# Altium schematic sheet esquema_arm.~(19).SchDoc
size A4
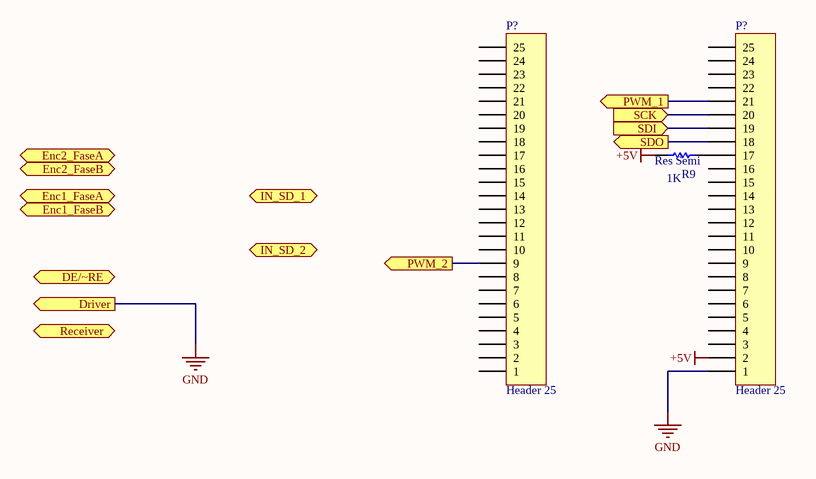
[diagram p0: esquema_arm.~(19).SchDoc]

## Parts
(Parts that share a designator on the sheet are numbered #1, #2 ... from top to bottom, then left to right.)
P?#1  Header 25  [HDR1X25]
P?#2  Header 25  [HDR1X25]
R9  Res Semi  value 1K  [1005[0402]]

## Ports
DE/~RE (out), Driver (out), Enc1_FaseA (in), Enc1_FaseB (in), Enc2_FaseA (in), Enc2_FaseB (in), IN_SD_1 (out), IN_SD_2 (out), PWM_1 (out), PWM_2 (out), Receiver (in), SCK (in), SDI (in), SDO (out)

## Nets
+5V: P?#2.2 R9.1
GND: P?#2.1 ; port Driver
PWM_1: P?#2.21 ; port PWM_1
PWM_2: P?#1.9 ; port PWM_2
SCK: P?#2.20 ; port SCK
SDI: P?#2.19 ; port SDI
SDO: P?#2.18 ; port SDO
NetP?#2_17: P?#2.17 R9.2

Not connected (* = marked no-connect by the designer): P?#1 1 2 3 4 5 6 7 8 10 11 12 13 14 15 16 17 18 19 20 21 22 23 24 25; P?#2 3 4 5 6 7 8 9 10 11 12 13 14 15 16 22 23 24 25

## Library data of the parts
P?#1 P?#2 = Header 25: Header, 25-Pin
R9 = Res Semi: Semiconductor Resistor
